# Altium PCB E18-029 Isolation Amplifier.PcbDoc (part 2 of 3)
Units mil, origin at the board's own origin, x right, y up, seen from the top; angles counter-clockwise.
Board outline 5740 x 5970 mil, 4 copper layers (Component Side, V+, V-, Ground), stack 33.234 mil thick; 359 components, 170 nets, 952 pads, 232 vias.
Unrouted connection lines stored in the file: 60.
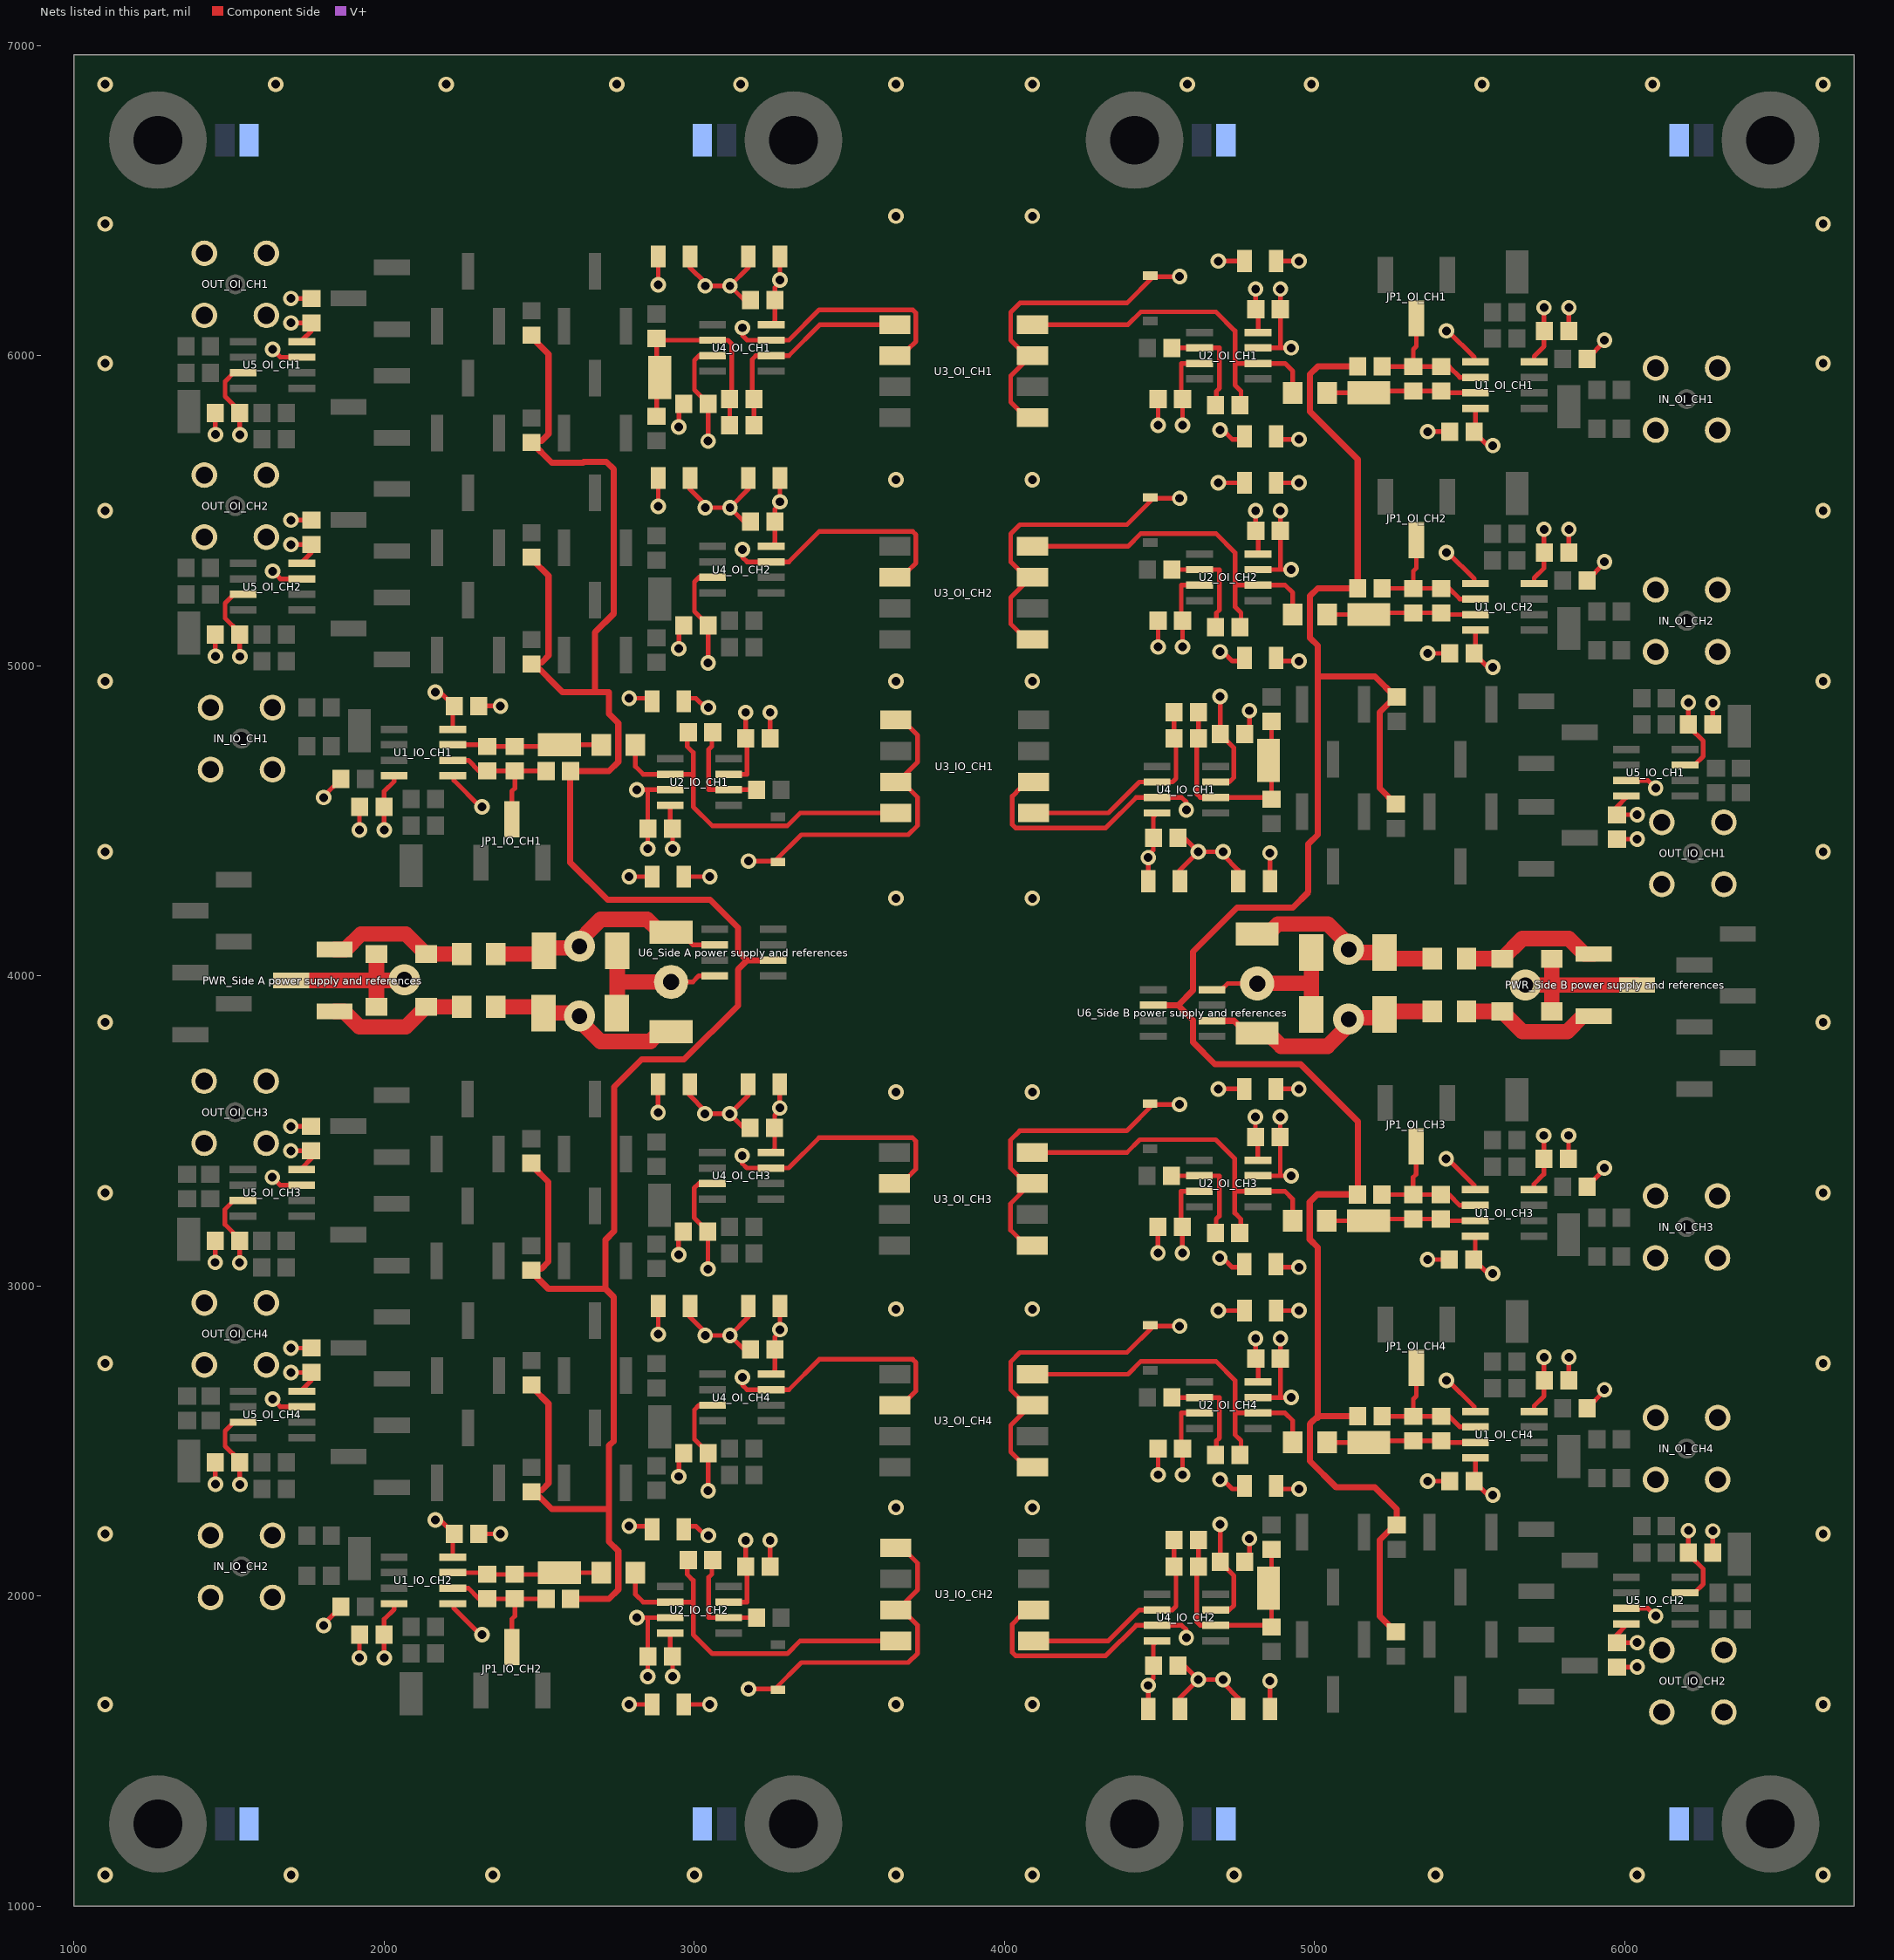
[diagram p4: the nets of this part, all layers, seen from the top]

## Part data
C1_IO_CH1 C1_IO_CH2 C1_OI_CH1 C1_OI_CH2 C1_OI_CH3 C1_OI_CH4 C2_IO_CH1 C2_IO_CH2 C2_OI_CH1 C2_OI_CH2 C2_OI_CH3 C2_OI_CH4 C3_IO_CH1 C3_IO_CH2 C3_OI_CH1 C3_OI_CH2 C3_OI_CH3 C3_OI_CH4 C4_IO_CH1 C4_IO_CH2 C4_OI_CH1 C4_OI_CH2 C4_OI_CH3 C4_OI_CH4 C6_IO_CH1 C6_IO_CH2 C6_OI_CH1 C6_OI_CH2 C6_OI_CH3 C6_OI_CH4 C7_IO_CH1 C7_IO_CH2 C7_OI_CH1 C7_OI_CH2 C7_OI_CH3 C7_OI_CH4 C8_IO_CH1 C8_IO_CH2 C8_OI_CH1 C8_OI_CH2 C8_OI_CH3 C8_OI_CH4 C9_IO_CH1 C9_IO_CH2 C9_OI_CH1 C9_OI_CH2 C9_OI_CH3 C9_OI_CH4 C14_IO_CH1 C14_IO_CH2 C14_OI_CH1 C14_OI_CH2 C14_OI_CH3 C14_OI_CH4 C15_IO_CH1 C15_IO_CH2 C15_OI_CH1 C15_OI_CH2 C15_OI_CH3 C15_OI_CH4 C16_IO_CH1 C16_IO_CH2 C16_OI_CH1 C16_OI_CH2 C16_OI_CH3 C16_OI_CH4 C17_IO_CH1 C17_IO_CH2 C17_OI_CH1 C17_OI_CH2 C17_OI_CH3 C17_OI_CH4: library part Cap, "Capacitor"
C10_IO_CH1 C10_IO_CH2 C10_OI_CH1 C10_OI_CH2 C10_OI_CH3 C10_OI_CH4 C11_IO_CH1 C11_IO_CH2 C11_OI_CH1 C11_OI_CH2 C11_OI_CH3 C11_OI_CH4 C12_IO_CH1 C12_IO_CH2 C12_OI_CH1 C12_OI_CH2 C12_OI_CH3 C12_OI_CH4 C13_IO_CH1 C13_IO_CH2 C13_OI_CH1 C13_OI_CH2 C13_OI_CH3 C13_OI_CH4: library part "Cap Pol3", "CAP TANT POLY 10UF 25V 1206"
"C18_Side A power supply and references" "C18_Side B power supply and references" "C19_Side A power supply and references" "C19_Side B power supply and references": library part "Cap Tant 100uF 10V", Manufacturer=AVX, Part Number=TCJE107M025R0080, Voltage=25V
D1_IO_CH1 D1_IO_CH2 D1_OI_CH1 D1_OI_CH2 D1_OI_CH3 D1_OI_CH4: "High Conductance Fast Diode", Manufacturer="Fairchild Semiconductor"
"D2_Side A power supply and references" "D2_Side B power supply and references" "D3_Side A power supply and references" "D3_Side B power supply and references": "Zener, 18V 1W SMAJ", Manufacturer=MCC, Part Number=SMAZ15-13-F
IN_IO_CH1 IN_IO_CH2 IN_OI_CH1 IN_OI_CH2 IN_OI_CH3 IN_OI_CH4 OUT_IO_CH1 OUT_IO_CH2 OUT_OI_CH1 OUT_OI_CH2 OUT_OI_CH3 OUT_OI_CH4: library part SMB_Male_Vertical, "SMA Male Vertical Mount", Manufacturer=Amphenol
JP1_IO_CH1 JP1_IO_CH2 JP1_OI_CH1 JP1_OI_CH2 JP1_OI_CH3 JP1_OI_CH4 JP2_IO_CH1 JP2_IO_CH2 JP2_OI_CH1 JP2_OI_CH2 JP2_OI_CH3 JP2_OI_CH4 JP3_IO_CH1 JP3_IO_CH2 JP3_OI_CH1 JP3_OI_CH2 JP3_OI_CH3 JP3_OI_CH4 "PWR_Side A power supply and references" "PWR_Side B power supply and references": library part Jumper3p, "3 Pin Jumper Header", Manufacturer="Generic Components"
JPA1 JPA2 JPA3 JPA4 JPB1 JPB2 JPB3 JPB4: library part Jumper2P_SMD, "2 Pin Jumper Solder Pads", Manufacturer="Generic Components"
Logo?: library part "Directive: Add UBC Logo to PCB", "UBC Logo"
MA1 MA2 MA3 MA4 MB1 MB2 MB3 MB4: library part "Mounting Pad", Manufacturer=AMP, Part No.=PAD_HV
PA PB: "0.1\" Spacing 1x6 Header", Manufacturer=AMP
R1_IO_CH1 R1_IO_CH2 R1_OI_CH1 R1_OI_CH2 R1_OI_CH3 R1_OI_CH4 R2_IO_CH1 R2_IO_CH2 R2_OI_CH1 R2_OI_CH2 R2_OI_CH3 R2_OI_CH4 R3_IO_CH1 R3_IO_CH2 R3_OI_CH1 R3_OI_CH2 R3_OI_CH3 R3_OI_CH4 R4_IO_CH1 R4_IO_CH2 R4_OI_CH1 R4_OI_CH2 R4_OI_CH3 R4_OI_CH4 R5_IO_CH1 R5_IO_CH2 R5_OI_CH1 R5_OI_CH2 R5_OI_CH3 R5_OI_CH4 R6_IO_CH1 R6_IO_CH2 R6_OI_CH1 R6_OI_CH2 R6_OI_CH3 R6_OI_CH4 R7_IO_CH1 R7_IO_CH2 R7_OI_CH1 R7_OI_CH2 R7_OI_CH3 R7_OI_CH4 R8_IO_CH1 R8_IO_CH2 R8_OI_CH1 R8_OI_CH2 R8_OI_CH3 R8_OI_CH4 R10_IO_CH1 R10_IO_CH2 R10_OI_CH1 R10_OI_CH2 R10_OI_CH3 R10_OI_CH4 R11_IO_CH1 R11_IO_CH2 R11_OI_CH1 R11_OI_CH2 R11_OI_CH3 R11_OI_CH4 R12_IO_CH1 R12_IO_CH2 R12_OI_CH1 R12_OI_CH2 R12_OI_CH3 R12_OI_CH4 R14_IO_CH1 R14_IO_CH2 R14_OI_CH1 R14_OI_CH2 R14_OI_CH3 R14_OI_CH4 R15_IO_CH1 R15_IO_CH2 R15_OI_CH1 R15_OI_CH2 R15_OI_CH3 R15_OI_CH4 R17_IO_CH1 R17_IO_CH2 R17_OI_CH1 R17_OI_CH2 R17_OI_CH3 R17_OI_CH4 R19_IO_CH1 R19_IO_CH2 R19_OI_CH1 R19_OI_CH2 R19_OI_CH3 R19_OI_CH4 R20_IO_CH1 R20_IO_CH2 R20_OI_CH1 R20_OI_CH2 R20_OI_CH3 R20_OI_CH4 R21_IO_CH1 R21_IO_CH2 R21_OI_CH1 R21_OI_CH2 R21_OI_CH3 R21_OI_CH4 "R27_Side A power supply and references" "R27_Side B power supply and references" "R28_Side A power supply and references" "R28_Side B power supply and references": library part Res1, "Resistor"
R9_IO_CH1 R9_IO_CH2 R9_OI_CH1 R9_OI_CH2 R9_OI_CH3 R9_OI_CH4 R13_IO_CH1 R13_IO_CH2 R13_OI_CH1 R13_OI_CH2 R13_OI_CH3 R13_OI_CH4 R16_IO_CH1 R16_IO_CH2 R16_OI_CH1 R16_OI_CH2 R16_OI_CH3 R16_OI_CH4 R18_IO_CH1 R18_IO_CH2 R18_OI_CH1 R18_OI_CH2 R18_OI_CH3 R18_OI_CH4: "SMD POT", Manufacturer=Vishay, Part Number=TS63Y
TP1_IO_CH1 TP1_IO_CH2 TP1_OI_CH1 TP1_OI_CH2 TP1_OI_CH3 TP1_OI_CH4 TP2_IO_CH1 TP2_IO_CH2 TP2_OI_CH1 TP2_OI_CH2 TP2_OI_CH3 TP2_OI_CH4 TP3_IO_CH1 TP3_IO_CH2 TP3_OI_CH1 TP3_OI_CH2 TP3_OI_CH3 TP3_OI_CH4 TP4_IO_CH1 TP4_IO_CH2 TP4_OI_CH1 TP4_OI_CH2 TP4_OI_CH3 TP4_OI_CH4 TP5_IO_CH1 TP5_IO_CH2 TP5_OI_CH1 TP5_OI_CH2 TP5_OI_CH3 TP5_OI_CH4 "TP+_Side A power supply and references" "TP+_Side B power supply and references" "TP-_Side A power supply and references" "TP-_Side B power supply and references" "TPCOM_Side A power supply and references" "TPCOM_Side B power supply and references": library part "TP- Eyelet Terminal", "Eyelet Test Point (white)", Manufacturer=Vero, Part Number=20-313143A
U1_IO_CH1 U1_IO_CH2 U1_OI_CH1 U1_OI_CH2 U1_OI_CH3 U1_OI_CH4 U5_IO_CH1 U5_IO_CH2 U5_OI_CH1 U5_OI_CH2 U5_OI_CH3 U5_OI_CH4: "OVP and EMI Protected, Precision, / Low Noise and Bias Current Dual Op Amp", Manufacturer="Analog Devices"
U2_IO_CH1 U2_IO_CH2 U2_OI_CH1 U2_OI_CH2 U2_OI_CH3 U2_OI_CH4: "36V, 18MHz, Low Noise, JFET Op Amp", Manufacturer="Analog Devices"
U3_IO_CH1 U3_IO_CH2 U3_OI_CH1 U3_OI_CH2 U3_OI_CH3 U3_OI_CH4: "Analog Optocoupler", Manufacturer=Agilent
U4_IO_CH1 U4_IO_CH2 U4_OI_CH1 U4_OI_CH2 U4_OI_CH3 U4_OI_CH4: "36V, 18MHz, Low Noise, JFET Op Amp", Manufacturer="Analog Devices", Part Number=AD548KR
"U6_Side A power supply and references" "U6_Side B power supply and references": "2ppm/°C, Low-Noise, +10V Voltage Reference", Manufacturer=Maxim, Part Number=MAX6325CSA

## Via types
v1: diameter 50, hole 28, Component Side to Ground, tented both sides, 226 vias
v2: diameter 100, hole 50, Component Side to Ground, tented both sides, 6 vias

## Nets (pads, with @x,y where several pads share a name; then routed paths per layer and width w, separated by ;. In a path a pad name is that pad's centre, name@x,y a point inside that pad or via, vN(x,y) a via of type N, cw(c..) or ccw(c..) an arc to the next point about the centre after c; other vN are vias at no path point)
+10REFA: "U6_Side A power supply and references.6" R1_IO_CH1.2 R1_IO_CH2.2 R8_OI_CH1.2 R8_OI_CH2.2 R8_OI_CH3.2 R8_OI_CH4.2 R11_OI_CH1.2 R11_OI_CH2.2 R11_OI_CH3.2 R11_OI_CH4.2 | length 7465.8
  Component Side w20: R11_OI_CH1.2@2475,5720 2540,5655 2641.11,5655 2643.33,5657.22 2716.67,5657.22 2740.69,5633.2 2740.69,5168.65 2680,5107.97 2680,4915.63 ; R11_OI_CH3.2@2477.83,3055.63 2507.17,3055.63 2529.37,3077.83 2529.37,3335 R8_OI_CH3.2@2479.37,3385 ; R11_OI_CH4.2@2478.46,2340.63 2507.8,2340.63 2530,2362.83 2530,2620 R8_OI_CH4.2@2480,2670 ; R11_OI_CH2.2@2478.46,5010.63 2507.8,5010.63 2530,5032.83 2530,5290 R8_OI_CH2.2@2480,5340 ; R11_OI_CH1.2@2478.46,5725.63 2507.8,5725.63 2530,5747.83 2530,6005 R8_OI_CH1.2@2480,6055 ; R11_OI_CH3.2@2479.37,3055 2479.37,3040.63 2530,2990 2713.89,2990 ; R11_OI_CH4.2@2480,2335 2480,2340 2540,2280 2725,2280 ; R11_OI_CH2.2@2480,5005 2480,5010 2574.37,4915.63 ; R11_OI_CH1.2@2480,5720 R11_OI_CH1.2@2480,5725 ; 2575,4915 2725,4915 2725,4845 2755,4815 2755,4690 2725,4660 R1_IO_CH1.2@2600.91,4660 2600,4660 2600,4365 2720,4245 3051.09,4245 3140.9,4155.18 3140.9,4079.1 3170,4050 ; R1_IO_CH2.2@2600,1990 R1_IO_CH2.2@2600.91,1990 2725,1990 2755,2020 2755,2145 2725,2175 2725,2280 ; 2740,2500 2725,2485 2725,2280 ; 2740.69,2498.65 2740.69,2963.2 2713.89,2990 ; 3254.49,4050 3170,4050 ; 2713.89,2990 2713.89,3148.89 2741.68,3176.68 2741.68,3641.68 2830,3730 2966.95,3730 3140.67,3903.72 3140.67,4020.67 3170,4050
+10REFB: "U6_Side B power supply and references.6" R1_OI_CH1.2 R1_OI_CH2.2 R1_OI_CH3.2 R1_OI_CH4.2 R8_IO_CH1.2 R8_IO_CH2.2 R11_IO_CH1.2 R11_IO_CH2.2 | length 6388
  Component Side w20: 4480.51,3905 4560,3905 ; 5010,2575 5010,2580 ; R1_OI_CH3.2@5134.37,3295 5009.37,3295 4984.37,3270 4984.37,3150 5010,3124.37 5010,2580 ; R1_OI_CH4.2@5135,2580 5010,2580 ; R1_OI_CH2.2@5135,5250 5010,5250 4985,5225 4985,5090 5010,5065 5010,4965 ; R1_OI_CH1.2@5135,5965 5010,5965 4985,5940 4985,5820 5139.09,5665.91 R1_OI_CH2.2@5139.09,5250 ; R1_OI_CH3.2@5140,3295 5140,3530 4955,3715 4678.91,3715 4608.18,3785.73 4608.18,3856.82 4560,3905 ; R8_IO_CH2.2@5260,1885 5210,1935 5210,2180 5259.37,2229.37 R11_IO_CH2.2@5265,2229.37 ; R8_IO_CH1.2@5260,4555 5210,4605 5210,4850 5259.37,4899.37 R11_IO_CH1.2@5265,4899.37 ; R11_IO_CH1.2@5260,4900 5195,4965 5010,4965 ; R11_IO_CH2.2@5265,2230 5265,2280 5195,2350 5070,2350 4985,2435 4985,2555 5010,2580 ; 4560,3905 4608.18,3953.18 4608.18,4078.18 4750,4220 4930,4220 4980,4270 4980,4425 5010,4455 5010,4965
+15A: "C18_Side A power supply and references.1" "R27_Side A power supply and references.1" "TP+_Side A power supply and references.1" "U6_Side A power supply and references.2" C6_IO_CH1.2 C6_IO_CH2.2 C7_IO_CH1.2 C7_IO_CH2.2 C8_OI_CH1.2 C8_OI_CH2.2 C8_OI_CH3.2 C8_OI_CH4.2 C9_OI_CH1.2 C9_OI_CH2.2 C9_OI_CH3.2 C9_OI_CH4.2 C10_IO_CH1.1 C10_IO_CH2.1 C11_OI_CH1.1 C11_OI_CH2.1 C11_OI_CH3.1 C11_OI_CH4.1 U1_IO_CH1.8 U1_IO_CH2.8 U2_IO_CH1.7 U2_IO_CH2.7 U4_OI_CH1.7 U4_OI_CH2.7 U4_OI_CH3.7 U4_OI_CH4.7 U5_OI_CH1.7 U5_OI_CH2.7 U5_OI_CH3.7 U5_OI_CH4.7 | length 4671.8
  Component Side w15: C9_OI_CH3.2@1516.07,3160.76 1518.61,3160.76 C9_OI_CH3.2@1534.37,3145 ; C9_OI_CH4.2@1516.7,2445.76 1519.24,2445.76 C9_OI_CH4.2@1535,2430 ; C9_OI_CH2.2@1516.7,5115.76 1519.24,5115.76 C9_OI_CH2.2@1535,5100 ; C9_OI_CH1.2@1516.7,5830.76 1519.24,5830.76 C9_OI_CH1.2@1535,5815 ; C9_OI_CH3.2@1529.37,3155 1486.07,3198.3 1486.07,3246.7 U5_OI_CH3.7@1514.37,3275 ; C9_OI_CH4.2@1530,2440 1486.7,2483.3 1486.7,2531.7 U5_OI_CH4.7@1515,2560 ; C9_OI_CH2.2@1530,5110 1486.7,5153.3 1486.7,5201.7 U5_OI_CH2.7@1515,5230 ; C9_OI_CH1.2@1530,5825 1486.7,5868.3 1486.7,5916.7 U5_OI_CH1.7@1515,5945 ; v1(1533.74,3074.37) C9_OI_CH3.2@1533.74,3145 ; v1(1534.37,2359.37) C9_OI_CH4.2@1534.37,2430 ; v1(1534.37,5029.37) C9_OI_CH2.2@1534.37,5100 ; v1(1534.37,5744.37) C9_OI_CH1.2@1534.37,5815 ; v1(2165,2245) 2180.63,2245 C6_IO_CH2.2@2225.63,2200 ; v1(2165,4915) 2180.63,4915 C6_IO_CH1.2@2225.63,4870 ; U1_IO_CH2.8@2221.02,2125 2221.02,2196.02 C6_IO_CH2.2@2225,2200 ; U1_IO_CH1.8@2221.02,4795 2221.02,4866.02 C6_IO_CH1.2@2225,4870 ; v1(2883.19,3558.82) C11_OI_CH3.1@2883.19,3650 ; v1(2883.82,2843.82) C11_OI_CH4.1@2883.82,2935 ; v1(2883.82,5513.82) C11_OI_CH2.1@2883.82,5605 ; v1(2883.82,6228.82) C11_OI_CH1.1@2883.82,6320 ; C10_IO_CH2.1@2966.18,2225 3005,2225 3035,2195 v1(3045,2195) ; C10_IO_CH1.1@2966.18,4895 3005,4895 3035,4865 v1(3045,4865) ; 2985,4110 2995,4100 3065.51,4100 ; v1(3043.74,3054.37) C8_OI_CH3.2@3043.74,3175 ; v1(3044.37,2339.37) C8_OI_CH4.2@3044.37,2460 ; C8_OI_CH3.2@3044.37,3175 2999.54,3219.83 2999.54,3315.17 3014.37,3330 U4_OI_CH3.7@3058.35,3330 ; v1(3044.37,5009.37) C8_OI_CH2.2@3044.37,5130 ; v1(3044.37,5724.37) C8_OI_CH1.2@3044.37,5845 ; C8_OI_CH4.2@3045,2460 3000.17,2504.83 3000.17,2600.17 3015,2615 U4_OI_CH4.7@3058.98,2615 ; C8_OI_CH2.2@3045,5130 3000.17,5174.83 3000.17,5270.17 3015,5285 U4_OI_CH2.7@3058.98,5285 ; C8_OI_CH1.2@3045,5845 3000.17,5889.83 3000.17,5985.17 3015,6000 U4_OI_CH1.7@3058.98,6000 ; U2_IO_CH2.7@3111.02,1980 3170,1980 C7_IO_CH2.2@3170,2095 ; U2_IO_CH1.7@3111.02,4650 3170,4650 C7_IO_CH1.2@3170,4765 ; C7_IO_CH2.2@3165.63,2095 v1(3165.63,2179.37) ; C7_IO_CH1.2@3165.63,4765 v1(3165.63,4849.37) ; U5_OI_CH3.7@1514.37,3275 U5_OI_CH3.7@1544.88,3275 U5_OI_CH3.7@1514.37,3275 ; U5_OI_CH4.7@1515,2560 U5_OI_CH4.7@1545.51,2560 U5_OI_CH4.7@1515,2560 ; U5_OI_CH2.7@1515,5230 U5_OI_CH2.7@1545.51,5230 U5_OI_CH2.7@1515,5230 ; U5_OI_CH1.7@1515,5945 U5_OI_CH1.7@1545.51,5945 U5_OI_CH1.7@1515,5945
  Component Side w20: 2925,4140 2955,4140
  Component Side w50: 2360.12,4070 2495,4070 2515,4090 2606.13,4090 2698.18,4182.06 2847.94,4182.06 2880,4150
  other v2: 2630,4095
+15B: "C18_Side B power supply and references.1" "R27_Side B power supply and references.1" "TP+_Side B power supply and references.1" "U6_Side B power supply and references.2" C6_OI_CH1.2 C6_OI_CH2.2 C6_OI_CH3.2 C6_OI_CH4.2 C7_OI_CH1.2 C7_OI_CH2.2 C7_OI_CH3.2 C7_OI_CH4.2 C8_IO_CH1.2 C8_IO_CH2.2 C9_IO_CH1.2 C9_IO_CH2.2 C10_OI_CH1.1 C10_OI_CH2.1 C10_OI_CH3.1 C10_OI_CH4.1 C11_IO_CH1.1 C11_IO_CH2.1 U1_OI_CH1.8 U1_OI_CH2.8 U1_OI_CH3.8 U1_OI_CH4.8 U2_OI_CH1.7 U2_OI_CH2.7 U2_OI_CH3.7 U2_OI_CH4.7 U4_IO_CH1.7 U4_IO_CH2.7 U5_IO_CH1.7 U5_IO_CH2.7 | length 4251.4
  Component Side w15: C7_OI_CH3.2@4569.37,3190 4569.37,3305 U2_OI_CH3.7@4628.35,3305 ; C7_OI_CH4.2@4570,2475 4570,2590 U2_OI_CH4.7@4628.98,2590 ; C7_OI_CH2.2@4570,5145 4570,5260 U2_OI_CH2.7@4628.98,5260 ; C7_OI_CH1.2@4570,5860 4570,5975 U2_OI_CH1.7@4628.98,5975 ; v1(4573.74,3105.63) C7_OI_CH3.2@4573.74,3190 ; v1(4574.37,2390.63) C7_OI_CH4.2@4574.37,2475 ; v1(4574.37,5060.63) C7_OI_CH2.2@4574.37,5145 ; v1(4574.37,5775.63) C7_OI_CH1.2@4574.37,5860 ; U4_IO_CH2.7@4681.02,1955 4725,1955 4739.83,1969.83 4739.83,2065.17 C8_IO_CH2.2@4695,2110 ; U4_IO_CH1.7@4681.02,4625 4725,4625 4739.83,4639.83 4739.83,4735.17 C8_IO_CH1.2@4695,4780 ; v1(4694.37,3090) 4704.37,3090 4734.37,3060 C10_OI_CH3.1@4773.19,3060 ; v1(4695,2375) 4705,2375 4735,2345 C10_OI_CH4.1@4773.82,2345 ; v1(4695,5045) 4705,5045 4735,5015 C10_OI_CH2.1@4773.82,5015 ; v1(4695,5760) 4705,5760 4735,5730 C10_OI_CH1.1@4773.82,5730 ; C8_IO_CH2.2@4695.63,2110 v1(4695.63,2230.63) ; C8_IO_CH1.2@4695.63,4780 v1(4695.63,4900.63) ; C11_IO_CH2.1@4856.18,1635 v1(4856.18,1726.18) ; C11_IO_CH1.1@4856.18,4305 v1(4856.18,4396.18) ; C6_OI_CH3.2@5513.74,3085 5558.74,3040 v1(5574.37,3040) ; C6_OI_CH4.2@5514.37,2370 5559.37,2325 v1(5575,2325) ; C6_OI_CH3.2@5514.37,3085 5518.35,3088.98 U1_OI_CH3.8@5518.35,3160 ; C6_OI_CH2.2@5514.37,5040 5559.37,4995 v1(5575,4995) ; C6_OI_CH1.2@5514.37,5755 5559.37,5710 v1(5575,5710) ; C6_OI_CH4.2@5515,2370 5518.98,2373.98 U1_OI_CH4.8@5518.98,2445 ; C6_OI_CH2.2@5515,5040 5518.98,5043.98 U1_OI_CH2.8@5518.98,5115 ; C6_OI_CH1.2@5515,5755 5518.98,5758.98 U1_OI_CH1.8@5518.98,5830 ; C9_IO_CH2.2@6205,2140 6220.76,2124.24 C9_IO_CH2.2@6223.3,2124.24 ; C9_IO_CH1.2@6205,4810 6220.76,4794.24 C9_IO_CH1.2@6223.3,4794.24 ; C9_IO_CH2.2@6205.63,2140 v1(6205.63,2210.63) ; C9_IO_CH1.2@6205.63,4810 v1(6205.63,4880.63) ; C9_IO_CH2.2@6210,2130 6253.3,2086.7 6253.3,2038.3 U5_IO_CH2.7@6225,2010 ; C9_IO_CH1.2@6210,4800 6253.3,4756.7 6253.3,4708.3 U5_IO_CH1.7@6225,4680 ; U5_IO_CH2.7@6225,2010 U5_IO_CH2.7@6194.49,2010 U5_IO_CH2.7@6225,2010 ; U5_IO_CH1.7@6225,4680 U5_IO_CH1.7@6194.49,4680 U5_IO_CH1.7@6225,4680
  Component Side w20: 4665,3855 4669.49,3855 4740,3855 4780,3815 4815,3815
  Component Side w50: 4860,3805 4892.06,3772.94 5041.82,3772.94 5133.87,3865 5225,3865 5245,3885 5379.88,3885
  other v2: 5110,3860
"+Vin_Side A power supply and references": "D2_Side A power supply and references.2" "PWR_Side A power supply and references.1" "R27_Side A power supply and references.2" | length 457.6
  Component Side w50: 1840,4085 1875,4085 1925,4135 2070,4135 2135,4070 2249.88,4070 2250,4070
"+Vin_Side B power supply and references": "D2_Side B power supply and references.2" "PWR_Side B power supply and references.1" "R27_Side B power supply and references.2" | length 457.6
  Component Side w50: 5490,3885 5490.12,3885 5605,3885 5670,3820 5815,3820 5865,3870 5900,3870
-15A: "C19_Side A power supply and references.2" "R28_Side A power supply and references.1" "TP-_Side A power supply and references.1" C12_IO_CH1.2 C12_IO_CH2.2 C13_OI_CH1.2 C13_OI_CH2.2 C13_OI_CH3.2 C13_OI_CH4.2 C14_IO_CH1.2 C14_IO_CH2.2 C15_IO_CH1.2 C15_IO_CH2.2 C16_OI_CH1.2 C16_OI_CH2.2 C16_OI_CH3.2 C16_OI_CH4.2 C17_OI_CH1.2 C17_OI_CH2.2 C17_OI_CH3.2 C17_OI_CH4.2 U1_IO_CH1.4 U1_IO_CH2.4 U2_IO_CH1.4 U2_IO_CH2.4 U4_OI_CH1.4 U4_OI_CH2.4 U4_OI_CH3.4 U4_OI_CH4.4 U5_OI_CH1.4 U5_OI_CH2.4 U5_OI_CH3.4 U5_OI_CH4.4 | length 2904.5
  Component Side w15: v1(1698.74,3435.63) C17_OI_CH3.2@1764.37,3435.63 ; v1(1699.37,2720.63) C17_OI_CH4.2@1765,2720.63 ; v1(1699.37,5390.63) C17_OI_CH2.2@1765,5390.63 ; v1(1699.37,6105.63) C17_OI_CH1.2@1765,6105.63 ; U5_OI_CH3.4@1733.86,3375 1733.86,3379.49 1764.37,3410 C17_OI_CH3.2@1764.37,3435 ; U5_OI_CH4.4@1734.49,2660 1734.49,2664.49 1765,2695 C17_OI_CH4.2@1765,2720 ; U5_OI_CH2.4@1734.49,5330 1734.49,5334.49 1765,5365 C17_OI_CH2.2@1765,5390 ; U5_OI_CH1.4@1734.49,6045 1734.49,6049.49 1765,6080 C17_OI_CH1.2@1765,6105 ; C14_IO_CH2.2@1999.37,1875 2000,1874.37 v1(2000,1800) ; C14_IO_CH1.2@1999.37,4545 2000,4544.37 v1(2000,4470) ; C14_IO_CH2.2@2000,1875 2000,1925 2032.05,1957.05 U1_IO_CH2.4@2032.05,1975 ; C14_IO_CH1.2@2000,4545 2000,4595 2032.05,4627.05 U1_IO_CH1.4@2032.05,4645 ; U2_IO_CH2.4@2922.05,1880 2922.05,1812.95 C15_IO_CH2.2@2930,1805 ; U2_IO_CH1.4@2922.05,4550 2922.05,4482.95 C15_IO_CH1.2@2930,4475 ; C15_IO_CH2.2@2929.37,1805 2930,1804.37 v1(2930,1740) ; C15_IO_CH1.2@2929.37,4475 2930,4474.37 v1(2930,4410) ; C12_IO_CH2.2@2966.18,1650 v1(3050,1650) ; C12_IO_CH1.2@2966.18,4320 v1(3050,4320) ; U4_OI_CH3.4@3247.32,3430 3259.37,3442.05 3259.37,3550 3275.55,3566.18 v1(3275.55,3573.82) C13_OI_CH3.2@3275.55,3650 ; U4_OI_CH4.4@3247.95,2715 3260,2727.05 3260,2835 3276.18,2851.18 v1(3276.18,2858.82) C13_OI_CH4.2@3276.18,2935 ; U4_OI_CH2.4@3247.95,5385 3260,5397.05 3260,5505 3276.18,5521.18 v1(3276.18,5528.82) C13_OI_CH2.2@3276.18,5605 ; U4_OI_CH1.4@3247.95,6100 3260,6112.05 3260,6220 3276.18,6236.18 v1(3276.18,6243.82) C13_OI_CH1.2@3276.18,6320
  Component Side w50: 2360.12,3900 2490,3900 2515,3875 ; 2513.78,3880 2604.91,3880 2696.96,3787.94 2857.94,3787.94 2890,3820
  other v2: 2630,3870
-15B: "C19_Side B power supply and references.2" "R28_Side B power supply and references.1" "TP-_Side B power supply and references.1" C12_OI_CH1.2 C12_OI_CH2.2 C12_OI_CH3.2 C12_OI_CH4.2 C13_IO_CH1.2 C13_IO_CH2.2 C14_OI_CH1.2 C14_OI_CH2.2 C14_OI_CH3.2 C14_OI_CH4.2 C15_OI_CH1.2 C15_OI_CH2.2 C15_OI_CH3.2 C15_OI_CH4.2 C16_IO_CH1.2 C16_IO_CH2.2 C17_IO_CH1.2 C17_IO_CH2.2 U1_OI_CH1.4 U1_OI_CH2.4 U1_OI_CH3.4 U1_OI_CH4.4 U2_OI_CH1.4 U2_OI_CH2.4 U2_OI_CH3.4 U2_OI_CH4.4 U4_IO_CH1.4 U4_IO_CH2.4 U5_IO_CH1.4 U5_IO_CH2.4 | length 2996.4
  Component Side w15: C13_IO_CH2.2@4463.82,1635 v1(4463.82,1711.18) 4463.82,1718.82 4480,1735 4480,1842.95 U4_IO_CH2.4@4492.05,1855 ; C13_IO_CH1.2@4463.82,4305 v1(4463.82,4381.18) 4463.82,4388.82 4480,4405 4480,4512.95 U4_IO_CH1.4@4492.05,4525 ; v1(4689.37,3635) C12_OI_CH3.2@4773.19,3635 ; v1(4690,2920) C12_OI_CH4.2@4773.82,2920 ; v1(4690,5590) C12_OI_CH2.2@4773.82,5590 ; v1(4690,6305) C12_OI_CH1.2@4773.82,6305 ; C15_OI_CH3.2@4809.37,3480 4817.32,3472.05 U2_OI_CH3.4@4817.32,3405 ; v1(4809.37,3545) 4809.37,3480.63 C15_OI_CH3.2@4810,3480 ; C15_OI_CH4.2@4810,2765 4817.95,2757.05 U2_OI_CH4.4@4817.95,2690 ; v1(4810,2830) 4810,2765.63 C15_OI_CH4.2@4810.63,2765 ; C15_OI_CH2.2@4810,5435 4817.95,5427.05 U2_OI_CH2.4@4817.95,5360 ; v1(4810,5500) 4810,5435.63 C15_OI_CH2.2@4810.63,5435 ; C15_OI_CH1.2@4810,6150 4817.95,6142.05 U2_OI_CH1.4@4817.95,6075 ; v1(4810,6215) 4810,6150.63 C15_OI_CH1.2@4810.63,6150 ; U1_OI_CH3.4@5707.32,3310 5707.32,3327.95 5739.37,3360 C14_OI_CH3.2@5739.37,3410 ; U1_OI_CH4.4@5707.95,2595 5707.95,2612.95 5740,2645 C14_OI_CH4.2@5740,2695 ; U1_OI_CH2.4@5707.95,5265 5707.95,5282.95 5740,5315 C14_OI_CH2.2@5740,5365 ; U1_OI_CH1.4@5707.95,5980 5707.95,5997.95 5740,6030 C14_OI_CH1.2@5740,6080 ; v1(5739.37,3485) 5739.37,3410.63 C14_OI_CH3.2@5740,3410 ; v1(5740,2770) 5740,2695.63 C14_OI_CH4.2@5740.63,2695 ; v1(5740,5440) 5740,5365.63 C14_OI_CH2.2@5740.63,5365 ; v1(5740,6155) 5740,6080.63 C14_OI_CH1.2@5740.63,6080 ; C17_IO_CH2.2@5975,1849.37 v1(6040.63,1849.37) ; C17_IO_CH2.2@5975,1850 5975,1875 6005.51,1905.51 U5_IO_CH2.4@6005.51,1910 ; C17_IO_CH1.2@5975,4519.37 v1(6040.63,4519.37) ; C17_IO_CH1.2@5975,4520 5975,4545 6005.51,4575.51 U5_IO_CH1.4@6005.51,4580
  Component Side w50: 4850,4135 4882.06,4167.06 5043.04,4167.06 5135.09,4075 5226.22,4075 ; 5225,4080 5250,4055 5379.88,4055
  other v2: 5110,4085
"-Vin_Side A power supply and references": "D3_Side A power supply and references.1" "PWR_Side A power supply and references.3" "R28_Side A power supply and references.2" | length 457.6
  Component Side w50: 1840,3885 1870,3885 1920,3835 2070,3835 2135,3900 2249.88,3900 2250,3900
"-Vin_Side B power supply and references": "D3_Side B power supply and references.1" "PWR_Side B power supply and references.3" "R28_Side B power supply and references.2" | length 457.6
  Component Side w50: 5490,4055 5490.12,4055 5605,4055 5670,4120 5820,4120 5870,4070 5900,4070
COMA: "C18_Side A power supply and references.2" "C19_Side A power supply and references.1" "D2_Side A power supply and references.1" "D3_Side A power supply and references.2" "PWR_Side A power supply and references.2" "TPCOM_Side A power supply and references.1" "U6_Side A power supply and references.4" C6_IO_CH1.1 C6_IO_CH2.1 C7_IO_CH1.1 C7_IO_CH2.1 C8_OI_CH1.1 C8_OI_CH2.1 C8_OI_CH3.1 C8_OI_CH4.1 C9_OI_CH1.1 C9_OI_CH2.1 C9_OI_CH3.1 C9_OI_CH4.1 C10_IO_CH1.2 C10_IO_CH2.2 C11_OI_CH1.2 C11_OI_CH2.2 C11_OI_CH3.2 C11_OI_CH4.2 C12_IO_CH1.1 C12_IO_CH2.1 C13_OI_CH1.1 C13_OI_CH2.1 C13_OI_CH3.1 C13_OI_CH4.1 C14_IO_CH1.1 C14_IO_CH2.1 C15_IO_CH1.1 C15_IO_CH2.1 C16_OI_CH1.1 C16_OI_CH2.1 C16_OI_CH3.1 C16_OI_CH4.1 C17_OI_CH1.1 C17_OI_CH2.1 C17_OI_CH3.1 C17_OI_CH4.1 D1_IO_CH1.1 D1_IO_CH2.1 IN_IO_CH1.2 IN_IO_CH2.2 JPA1.2 JPA2.2 JPA3.2 JPA4.2 OUT_OI_CH1.2 OUT_OI_CH2.2 OUT_OI_CH3.2 OUT_OI_CH4.2 R7_IO_CH1.1 R7_IO_CH2.1 U1_IO_CH1.5 U1_IO_CH2.5 U2_IO_CH1.3 U2_IO_CH2.3 U3_IO_CH1.1 U3_IO_CH1.3 U3_IO_CH2.1 U3_IO_CH2.3 U3_OI_CH1.6 U3_OI_CH2.6 U3_OI_CH3.6 U3_OI_CH4.6 U4_OI_CH1.3 U4_OI_CH2.3 U4_OI_CH3.3 U4_OI_CH4.3 U5_OI_CH1.3 U5_OI_CH2.3 U5_OI_CH3.3 U5_OI_CH4.3 | length 10932.8
  Component Side w15: v1(1455,3075.63) C9_OI_CH3.1@1455,3145 ; v1(1455.63,2360.63) C9_OI_CH4.1@1455.63,2430 ; v1(1455.63,5030.63) C9_OI_CH2.1@1455.63,5100 ; v1(1455.63,5745.63) C9_OI_CH1.1@1455.63,5815 ; v1(1639.37,3350) 1664.37,3325 U5_OI_CH3.3@1733.86,3325 ; v1(1640,2635) 1665,2610 U5_OI_CH4.3@1734.49,2610 ; v1(1640,5305) 1665,5280 U5_OI_CH2.3@1734.49,5280 ; v1(1640,6020) 1665,5995 U5_OI_CH1.3@1734.49,5995 ; v1(1698.74,3514.37) C17_OI_CH3.1@1764.37,3514.37 ; v1(1699.37,2799.37) C17_OI_CH4.1@1765,2799.37 ; v1(1699.37,5469.37) C17_OI_CH2.1@1765,5469.37 ; v1(1699.37,6184.37) C17_OI_CH1.1@1765,6184.37 ; v1(1805,1905) 1805,1909.37 R7_IO_CH2.1@1860.63,1965 ; v1(1805,4575) 1805,4579.37 R7_IO_CH1.1@1860.63,4635 ; v1(1920,1800) 1920,1874.37 C14_IO_CH2.1@1920.63,1875 ; v1(1920,4470) 1920,4544.37 C14_IO_CH1.1@1920.63,4545 ; U1_IO_CH2.5@2221.02,1975 2225,1971.02 2225,1960 2310,1875 v1(2315,1875) ; U1_IO_CH1.5@2221.02,4645 2225,4641.02 2225,4630 2310,4545 v1(2315,4545) ; C6_IO_CH2.1@2304.37,2200 v1(2375,2200) ; C6_IO_CH1.1@2304.37,4870 v1(2375,4870) ; v1(2790,1650) C12_IO_CH2.1@2863.82,1650 ; v1(2790,2225) C10_IO_CH2.2@2858.82,2225 ; v1(2790,4320) C12_IO_CH1.1@2863.82,4320 ; v1(2790,4895) C10_IO_CH1.2@2858.82,4895 ; v1(2815,1930) 2850,1930 ; v1(2815,4600) 2850,4600 ; v1(2850,1740) 2850,1930 ; v1(2850,4410) 2850,4600 ; U2_IO_CH2.3@2922.05,1930 2850,1930 ; U2_IO_CH1.3@2922.05,4600 2850,4600 ; 2925,3980 2995,3980 3015,4000 3065.51,4000 ; v1(2949.37,3100) 2949.37,3159.37 C8_OI_CH3.1@2965,3175 ; v1(2950,2385) 2950,2444.37 C8_OI_CH4.1@2965.63,2460 ; v1(2950,5055) 2950,5114.37 C8_OI_CH2.1@2965.63,5130 ; v1(2950,5770) 2950,5829.37 C8_OI_CH1.1@2965.63,5845 ; C11_OI_CH3.2@2984.37,3615 3034.37,3565 v1(3034.37,3555) v1(3114.37,3555) ; C11_OI_CH4.2@2985,2900 3035,2850 v1(3035,2840) v1(3115,2840) ; C11_OI_CH2.2@2985,5570 3035,5520 v1(3035,5510) v1(3115,5510) ; C11_OI_CH1.2@2985,6285 3035,6235 v1(3035,6225) v1(3115,6225) ; v1(3154.37,3420) 3154.37,3395 3169.37,3380 U4_OI_CH3.3@3247.32,3380 3304.37,3380 3402.37,3478 3703.29,3478 3713.83,3467.46 3713.83,3376 3687.83,3350 3665.83,3350 U3_OI_CH3.6@3645.83,3330 U3_OI_CH3.6@3624.37,3330 ; v1(3155,2705) 3155,2680 3170,2665 U4_OI_CH4.3@3247.95,2665 3305,2665 3403,2763 3703.92,2763 3714.46,2752.46 3714.46,2661 3688.46,2635 3666.46,2635 U3_OI_CH4.6@3646.46,2615 U3_OI_CH4.6@3625,2615 ; v1(3155,5375) 3155,5350 3170,5335 U4_OI_CH2.3@3247.95,5335 3305,5335 3403,5433 3703.92,5433 3714.46,5422.46 3714.46,5331 3688.46,5305 3666.46,5305 U3_OI_CH2.6@3646.46,5285 U3_OI_CH2.6@3625,5285 ; v1(3155,6090) 3155,6065 3170,6050 U4_OI_CH1.3@3247.95,6050 3305,6050 3403,6148 3703.92,6148 3714.46,6137.46 3714.46,6046 3688.46,6020 3666.46,6020 U3_OI_CH1.6@3646.46,6000 U3_OI_CH1.6@3625,6000 ; C13_OI_CH3.1@3174.37,3620 3174.37,3615 v1(3114.37,3555) ; v1(3175,1700) 3260,1700 3345,1785 3690,1785 3720,1815 3720,1905 U3_IO_CH2.3@3662.5,1962.5 ; C13_OI_CH4.1@3175,2905 3175,2900 v1(3115,2840) ; v1(3175,4370) 3260,4370 3345,4455 3690,4455 3720,4485 3720,4575 U3_IO_CH1.3@3662.5,4632.5 ; C13_OI_CH2.1@3175,5575 3175,5570 v1(3115,5510) ; C13_OI_CH1.1@3175,6290 3175,6285 v1(3115,6225) ; C16_OI_CH3.1@3180,3510 3159.37,3510 v1(3114.37,3555) ; C16_OI_CH4.1@3180.63,2795 3160,2795 v1(3115,2840) ; C16_OI_CH2.1@3180.63,5465 3160,5465 v1(3115,5510) ; C16_OI_CH1.1@3180.63,6180 3160,6180 v1(3115,6225) ; C7_IO_CH2.1@3244.37,2095 v1(3244.37,2179.37) ; C7_IO_CH1.1@3244.37,4765 v1(3244.37,4849.37) ; U3_IO_CH2.3@3649.54,1955 U3_IO_CH2.3@3651.46,1955 ; U3_IO_CH1.3@3649.54,4625 U3_IO_CH1.3@3651.46,4625 ; U3_IO_CH2.1@3651.54,2155 3670,2155 3720,2105 3720,2020.01 U3_IO_CH2.3@3662.5,1962.5 ; U3_IO_CH1.1@3651.54,4825 3670,4825 3720,4775 3720,4690.01 U3_IO_CH1.3@3662.5,4632.5 ; U3_IO_CH2.3@3662.5,1962.5 3659.77,1965.23 3654.99,1970.01 3654.99,1955 U3_IO_CH2.3@3662.5,1962.5 ; U3_IO_CH1.3@3662.5,4632.5 3659.77,4635.23 3654.99,4640.01 3654.99,4625 U3_IO_CH1.3@3662.5,4632.5
  Component Side w50: 1700,3985 1975,3985 ; 1975,3900 1975,3985 ; 1975,4070 1975,3985 ; v2(2065,3987.5) 2062.5,3985 1975,3985 ; 2750,3880 2751.22,3881.22 2751.22,3980 ; 2751.22,4080 2751.22,3980 ; 2925,3980 2751.22,3980
  V+ w15: v1(3244.37,2179.37) v1@3245,2180 ; v1(3244.37,4849.37) v1@3245,4850
  other v1: 1100,1100 1700,1100 2350,1100 3000,1100 3650,1100 1100,1650 3650,1650 1100,2200 3650,2285 1100,2750 3650,2925 1100,3300 3650,3625 1100,3850 3650,4250 1100,4400 1100,4950 3650,4950 1100,5500 3650,5600 1100,5975 1100,6425 3650,6450 1100,6875 1650,6875 2200,6875 2750,6875 3150,6875 3650,6875
COMB: "C18_Side B power supply and references.2" "C19_Side B power supply and references.1" "D2_Side B power supply and references.1" "D3_Side B power supply and references.2" "PWR_Side B power supply and references.2" "TPCOM_Side B power supply and references.1" "U6_Side B power supply and references.4" C6_OI_CH1.1 C6_OI_CH2.1 C6_OI_CH3.1 C6_OI_CH4.1 C7_OI_CH1.1 C7_OI_CH2.1 C7_OI_CH3.1 C7_OI_CH4.1 C8_IO_CH1.1 C8_IO_CH2.1 C9_IO_CH1.1 C9_IO_CH2.1 C10_OI_CH1.2 C10_OI_CH2.2 C10_OI_CH3.2 C10_OI_CH4.2 C11_IO_CH1.2 C11_IO_CH2.2 C12_OI_CH1.1 C12_OI_CH2.1 C12_OI_CH3.1 C12_OI_CH4.1 C13_IO_CH1.1 C13_IO_CH2.1 C14_OI_CH1.1 C14_OI_CH2.1 C14_OI_CH3.1 C14_OI_CH4.1 C15_OI_CH1.1 C15_OI_CH2.1 C15_OI_CH3.1 C15_OI_CH4.1 C16_IO_CH1.1 C16_IO_CH2.1 C17_IO_CH1.1 C17_IO_CH2.1 D1_OI_CH1.1 D1_OI_CH2.1 D1_OI_CH3.1 D1_OI_CH4.1 IN_OI_CH1.2 IN_OI_CH2.2 IN_OI_CH3.2 IN_OI_CH4.2 JPB1.2 JPB2.2 JPB3.2 JPB4.2 OUT_IO_CH1.2 OUT_IO_CH2.2 R7_OI_CH1.1 R7_OI_CH2.1 R7_OI_CH3.1 R7_OI_CH4.1 U1_OI_CH1.5 U1_OI_CH2.5 U1_OI_CH3.5 U1_OI_CH4.5 U2_OI_CH1.3 U2_OI_CH2.3 U2_OI_CH3.3 U2_OI_CH4.3 U3_IO_CH1.6 U3_IO_CH2.6 U3_OI_CH1.1 U3_OI_CH1.3 U3_OI_CH2.1 U3_OI_CH2.3 U3_OI_CH3.1 U3_OI_CH3.3 U3_OI_CH4.1 U3_OI_CH4.3 U4_IO_CH1.3 U4_IO_CH2.3 U5_IO_CH1.3 U5_IO_CH2.3 | length 11852.3
  Component Side w15: U3_OI_CH3.1@4087.83,3130 4069.37,3130 4019.37,3180 4019.37,3264.99 U3_OI_CH3.3@4076.87,3322.5 ; U3_OI_CH3.3@4087.91,3330 U3_OI_CH3.3@4089.83,3330 ; U3_OI_CH4.1@4088.46,2415 4070,2415 4020,2465 4020,2549.99 U3_OI_CH4.3@4077.5,2607.5 ; U3_OI_CH2.1@4088.46,5085 4070,5085 4020,5135 4020,5219.99 U3_OI_CH2.3@4077.5,5277.5 ; U3_OI_CH1.1@4088.46,5800 4070,5800 4020,5850 4020,5934.99 U3_OI_CH1.3@4077.5,5992.5 ; U3_OI_CH4.3@4088.54,2615 U3_OI_CH4.3@4090.46,2615 ; U3_OI_CH2.3@4088.54,5285 U3_OI_CH2.3@4090.46,5285 ; U3_OI_CH1.3@4088.54,6000 U3_OI_CH1.3@4090.46,6000 ; U3_IO_CH2.6@4115,1955 U3_IO_CH2.6@4093.54,1955 4073.54,1935 4051.54,1935 4025.54,1909 4025.54,1817.54 4036.08,1807 4327,1807 4425,1905 U4_IO_CH2.3@4490,1905 ; U3_IO_CH1.6@4115,4625 U3_IO_CH1.6@4093.54,4625 4073.54,4605 4051.54,4605 4025.54,4579 4025.54,4487.54 4036.08,4477 4327,4477 4425,4575 U4_IO_CH1.3@4490,4575 ; U4_IO_CH2.3@4493.58,1905 4571.54,1905 4586.54,1890 v1(4586.54,1865) ; U4_IO_CH1.3@4493.58,4575 4571.54,4575 4586.54,4560 v1(4586.54,4535) ; v1(4495,3105.63) C7_OI_CH3.1@4495,3190 ; v1(4495.63,2390.63) C7_OI_CH4.1@4495.63,2475 ; v1(4495.63,5060.63) C7_OI_CH2.1@4495.63,5145 ; v1(4495.63,5775.63) C7_OI_CH1.1@4495.63,5860 ; C16_IO_CH2.1@4559.37,1775 4580,1775 v1(4625,1730) ; C16_IO_CH1.1@4559.37,4445 4580,4445 v1(4625,4400) ; v1(4564.37,3585) 4479.37,3585 4394.37,3500 4049.37,3500 4019.37,3470 4019.37,3380 U3_OI_CH3.3@4076.87,3322.5 ; C13_IO_CH2.1@4565,1665 4565,1670 v1(4625,1730) ; v1(4565,2870) 4480,2870 4395,2785 4050,2785 4020,2755 4020,2665 U3_OI_CH4.3@4077.5,2607.5 ; C13_IO_CH1.1@4565,4335 4565,4340 v1(4625,4400) ; v1(4565,5540) 4480,5540 4395,5455 4050,5455 4020,5425 4020,5335 U3_OI_CH2.3@4077.5,5277.5 ; v1(4565,6255) 4480,6255 4395,6170 4050,6170 4020,6140 4020,6050 U3_OI_CH1.3@4077.5,5992.5 ; 4669.49,3955 4700,3955 4720,3975 4815,3975 ; C11_IO_CH2.2@4755,1670 4705,1720 v1(4705,1730) v1(4625,1730) ; C11_IO_CH1.2@4755,4340 4705,4390 v1(4705,4400) v1(4625,4400) ; C8_IO_CH2.1@4774.37,2110 4790,2125.63 v1(4790,2185) ; C8_IO_CH1.1@4774.37,4780 4790,4795.63 v1(4790,4855) ; U2_OI_CH3.3@4817.32,3355 4889.37,3355 ; U2_OI_CH4.3@4817.95,2640 4890,2640 ; U2_OI_CH2.3@4817.95,5310 4890,5310 ; U2_OI_CH1.3@4817.95,6025 4890,6025 ; C12_OI_CH3.1@4875.55,3635 v1(4949.37,3635) ; C12_OI_CH4.1@4876.18,2920 v1(4950,2920) ; C12_OI_CH2.1@4876.18,5590 v1(4950,5590) ; C12_OI_CH1.1@4876.18,6305 v1(4950,6305) ; C10_OI_CH3.2@4880.55,3060 v1(4949.37,3060) ; C10_OI_CH4.2@4881.18,2345 v1(4950,2345) ; C10_OI_CH2.2@4881.18,5015 v1(4950,5015) ; C10_OI_CH1.2@4881.18,5730 v1(4950,5730) ; v1(4889.37,3545) 4889.37,3355 ; v1(4890,2830) 4890,2640 ; v1(4890,5500) 4890,5310 ; v1(4890,6215) 4890,6025 ; v1(4924.37,3355) 4889.37,3355 ; v1(4925,2640) 4890,2640 ; v1(4925,5310) 4890,5310 ; v1(4925,6025) 4890,6025 ; v1(5364.37,3085) C6_OI_CH3.1@5435,3085 ; v1(5365,2370) C6_OI_CH4.1@5435.63,2370 ; v1(5365,5040) C6_OI_CH2.1@5435.63,5040 ; v1(5365,5755) C6_OI_CH1.1@5435.63,5755 ; v1(5424.37,3410) 5429.37,3410 5514.37,3325 5514.37,3313.98 U1_OI_CH3.5@5518.35,3310 ; v1(5425,2695) 5430,2695 5515,2610 5515,2598.98 U1_OI_CH4.5@5518.98,2595 ; v1(5425,5365) 5430,5365 5515,5280 5515,5268.98 U1_OI_CH2.5@5518.98,5265 ; v1(5425,6080) 5430,6080 5515,5995 5515,5983.98 U1_OI_CH1.5@5518.98,5980 ; C14_OI_CH3.1@5818.74,3410 5819.37,3410.63 v1(5819.37,3485) ; C14_OI_CH4.1@5819.37,2695 5820,2695.63 v1(5820,2770) ; C14_OI_CH2.1@5819.37,5365 5820,5365.63 v1(5820,5440) ; C14_OI_CH1.1@5819.37,6080 5820,6080.63 v1(5820,6155) ; R7_OI_CH3.1@5878.74,3320 5934.37,3375.63 v1(5934.37,3380) ; R7_OI_CH4.1@5879.37,2605 5935,2660.63 v1(5935,2665) ; R7_OI_CH2.1@5879.37,5275 5935,5330.63 v1(5935,5335) ; R7_OI_CH1.1@5879.37,5990 5935,6045.63 v1(5935,6050) ; C17_IO_CH2.1@5975,1770.63 v1(6040.63,1770.63) ; C17_IO_CH1.1@5975,4440.63 v1(6040.63,4440.63) ; U5_IO_CH2.3@6005.51,1960 6075,1960 v1(6100,1935) ; U5_IO_CH1.3@6005.51,4630 6075,4630 v1(6100,4605) ; C9_IO_CH2.1@6284.37,2140 v1(6284.37,2209.37) ; C9_IO_CH1.1@6284.37,4810 v1(6284.37,4879.37) ; U3_OI_CH3.3@4076.87,3322.5 4084.38,3330 4084.38,3314.99 4079.6,3319.77 U3_OI_CH3.3@4076.87,3322.5 ; U3_OI_CH4.3@4077.5,2607.5 4085.01,2615 4085.01,2599.99 4080.23,2604.77 U3_OI_CH4.3@4077.5,2607.5 ; U3_OI_CH2.3@4077.5,5277.5 4085.01,5285 4085.01,5269.99 4080.23,5274.77 U3_OI_CH2.3@4077.5,5277.5 ; U3_OI_CH1.3@4077.5,5992.5 4085.01,6000 4085.01,5984.99 4080.23,5989.77 U3_OI_CH1.3@4077.5,5992.5
  Component Side w50: 4815,3975 4815.61,3975.61 4990,3975.61 ; 4988.78,3875 4990,3876.22 4990,3975.61 ; 4990,4075 4990,3975.61 ; v2(5680,3970) 5765,3970 ; 5765,3885 5765,3970 ; 5765,4055 5765,3970 ; 6040,3970 5765,3970
  V+ w15: v1@4494.37,3105 v1(4495,3105.63) ; v1@4495,2390 v1(4495.63,2390.63) ; v1@4495,5060 v1(4495.63,5060.63) ; v1@4495,5775 v1(4495.63,5775.63)
  other v1: 4090,1100 4740,1100 5390,1100 6040,1100 6640,1100 4090,1650 6640,1650 6640,2200 4090,2285 6640,2750 4090,2925 6640,3300 4090,3625 6640,3850 4090,4250 6640,4400 4090,4950 6640,4950 6640,5500 4090,5600 6640,5975 6640,6425 4090,6450 4090,6875 4590,6875 4990,6875 5540,6875 6090,6875 6640,6875
NetC1_IO_CH1_1: C1_IO_CH1.1 R2_IO_CH1.1 R4_IO_CH1.1 TP3_IO_CH1.1 U1_IO_CH1.7 | length 493.6
  Component Side w15: U1_IO_CH1.7@2221.02,4745 2331.54,4745 R2_IO_CH1.1@2336.54,4740 ; R2_IO_CH1.1@2331.54,4740 R2_IO_CH1.1@2332.17,4739.37 C1_IO_CH1.1@2421.54,4739.37 2559.37,4739.37 TP3_IO_CH1.1@2565,4745 R4_IO_CH1.1@2699.88,4745 R4_IO_CH1.1@2705,4745
NetC1_IO_CH1_2: C1_IO_CH1.2 JP1_IO_CH1.2 R1_IO_CH1.1 R2_IO_CH1.2 U1_IO_CH1.6 | length 472.4
  Component Side w15: U1_IO_CH1.6@2226.54,4695 2271.54,4695 2305.91,4660.63 2420.91,4660.63 2421.54,4660 2421.54,4605 2411.54,4595 JP1_IO_CH1.2@2411.54,4505 ; C1_IO_CH1.2@2421.54,4660.63 2524.37,4660.63 R1_IO_CH1.1@2525,4660
NetC1_IO_CH2_1: C1_IO_CH2.1 R2_IO_CH2.1 R4_IO_CH2.1 TP3_IO_CH2.1 U1_IO_CH2.7 | length 493.6
  Component Side w15: U1_IO_CH2.7@2221.02,2075 2331.54,2075 R2_IO_CH2.1@2336.54,2070 ; R2_IO_CH2.1@2331.54,2070 R2_IO_CH2.1@2332.17,2069.37 C1_IO_CH2.1@2421.54,2069.37 2559.37,2069.37 TP3_IO_CH2.1@2565,2075 R4_IO_CH2.1@2699.88,2075 R4_IO_CH2.1@2705,2075
NetC1_IO_CH2_2: C1_IO_CH2.2 JP1_IO_CH2.2 R1_IO_CH2.1 R2_IO_CH2.2 U1_IO_CH2.6 | length 472.4
  Component Side w15: U1_IO_CH2.6@2226.54,2025 2271.54,2025 2305.91,1990.63 2420.91,1990.63 2421.54,1990 2421.54,1935 2411.54,1925 JP1_IO_CH2.2@2411.54,1835 ; C1_IO_CH2.2@2421.54,1990.63 2524.37,1990.63 R1_IO_CH2.1@2525,1990
NetC1_OI_CH1_1: C1_OI_CH1.1 R2_OI_CH1.1 R4_OI_CH1.1 TP3_OI_CH1.1 U1_OI_CH1.7 | length 493.6
  Component Side w15: R4_OI_CH1.1@5035,5880 R4_OI_CH1.1@5040.12,5880 TP3_OI_CH1.1@5175,5880 5180.63,5885.63 C1_OI_CH1.1@5318.46,5885.63 R2_OI_CH1.1@5407.83,5885.63 R2_OI_CH1.1@5408.46,5885 ; R2_OI_CH1.1@5403.46,5885 5408.46,5880 U1_OI_CH1.7@5518.98,5880
NetC1_OI_CH1_2: C1_OI_CH1.2 JP1_OI_CH1.2 R1_OI_CH1.1 R2_OI_CH1.2 U1_OI_CH1.6 | length 472.4
  Component Side w15: R1_OI_CH1.1@5215,5965 5215.63,5964.37 C1_OI_CH1.2@5318.46,5964.37 ; JP1_OI_CH1.2@5328.46,6120 5328.46,6030 5318.46,6020 5318.46,5965 5319.09,5964.37 5434.09,5964.37 5468.46,5930 U1_OI_CH1.6@5513.46,5930
NetC1_OI_CH2_1: C1_OI_CH2.1 R2_OI_CH2.1 R4_OI_CH2.1 TP3_OI_CH2.1 U1_OI_CH2.7 | length 493.6
  Component Side w15: R4_OI_CH2.1@5035,5165 R4_OI_CH2.1@5040.12,5165 TP3_OI_CH2.1@5175,5165 5180.63,5170.63 C1_OI_CH2.1@5318.46,5170.63 R2_OI_CH2.1@5407.83,5170.63 R2_OI_CH2.1@5408.46,5170 ; R2_OI_CH2.1@5403.46,5170 5408.46,5165 U1_OI_CH2.7@5518.98,5165
NetC1_OI_CH2_2: C1_OI_CH2.2 JP1_OI_CH2.2 R1_OI_CH2.1 R2_OI_CH2.2 U1_OI_CH2.6 | length 472.4
  Component Side w15: R1_OI_CH2.1@5215,5250 5215.63,5249.37 C1_OI_CH2.2@5318.46,5249.37 ; JP1_OI_CH2.2@5328.46,5405 5328.46,5315 5318.46,5305 5318.46,5250 5319.09,5249.37 5434.09,5249.37 5468.46,5215 U1_OI_CH2.6@5513.46,5215
NetC1_OI_CH3_1: C1_OI_CH3.1 R2_OI_CH3.1 R4_OI_CH3.1 TP3_OI_CH3.1 U1_OI_CH3.7 | length 493.6
  Component Side w15: R4_OI_CH3.1@5034.37,3210 R4_OI_CH3.1@5039.49,3210 TP3_OI_CH3.1@5174.37,3210 5180,3215.63 C1_OI_CH3.1@5317.83,3215.63 R2_OI_CH3.1@5407.2,3215.63 R2_OI_CH3.1@5407.83,3215 ; R2_OI_CH3.1@5402.83,3215 5407.83,3210 U1_OI_CH3.7@5518.35,3210
NetC1_OI_CH3_2: C1_OI_CH3.2 JP1_OI_CH3.2 R1_OI_CH3.1 R2_OI_CH3.2 U1_OI_CH3.6 | length 472.4
  Component Side w15: R1_OI_CH3.1@5214.37,3295 5215,3294.37 C1_OI_CH3.2@5317.83,3294.37 ; JP1_OI_CH3.2@5327.83,3450 5327.83,3360 5317.83,3350 5317.83,3295 5318.46,3294.37 5433.46,3294.37 5467.83,3260 U1_OI_CH3.6@5512.83,3260
NetC1_OI_CH4_1: C1_OI_CH4.1 R2_OI_CH4.1 R4_OI_CH4.1 TP3_OI_CH4.1 U1_OI_CH4.7 | length 493.6
  Component Side w15: R4_OI_CH4.1@5035,2495 R4_OI_CH4.1@5040.12,2495 TP3_OI_CH4.1@5175,2495 5180.63,2500.63 C1_OI_CH4.1@5318.46,2500.63 R2_OI_CH4.1@5407.83,2500.63 R2_OI_CH4.1@5408.46,2500 ; R2_OI_CH4.1@5403.46,2500 5408.46,2495 U1_OI_CH4.7@5518.98,2495
NetC1_OI_CH4_2: C1_OI_CH4.2 JP1_OI_CH4.2 R1_OI_CH4.1 R2_OI_CH4.2 U1_OI_CH4.6 | length 472.4
  Component Side w15: R1_OI_CH4.1@5215,2580 5215.63,2579.37 C1_OI_CH4.2@5318.46,2579.37 ; JP1_OI_CH4.2@5328.46,2735 5328.46,2645 5318.46,2635 5318.46,2580 5319.09,2579.37 5434.09,2579.37 5468.46,2545 U1_OI_CH4.6@5513.46,2545
NetC2_IO_CH1_1: C2_IO_CH1.1 R5_IO_CH1.1 U2_IO_CH1.6 | length 342.6
  Component Side w15: C2_IO_CH1.1@3056.54,4780 3056.54,4740 3046.54,4730 3046.54,4600 U2_IO_CH1.6@3111.02,4600 R5_IO_CH1.1@3200.63,4600 R5_IO_CH1.1@3205,4600
NetC2_IO_CH1_2: C2_IO_CH1.2 R4_IO_CH1.2 U2_IO_CH1.2 U3_IO_CH1.4 | length 1217.6
  Component Side w15: R4_IO_CH1.2@2810.12,4745 2810.12,4674.88 2835,4650 U2_IO_CH1.2@2922.05,4650 2996.54,4650 ; C2_IO_CH1.2@2977.17,4780 2977.17,4739.37 2996.54,4720 2996.54,4650 ; U3_IO_CH1.4@3649.54,4525 U3_IO_CH1.4@3655,4525 ; U3_IO_CH1.4@3650,4510 3635,4525 3341.49,4525 3300.04,4483.55 3057.98,4483.55 2996.54,4545 2996.54,4650
NetC2_IO_CH2_1: C2_IO_CH2.1 R5_IO_CH2.1 U2_IO_CH2.6 | length 342.6
  Component Side w15: C2_IO_CH2.1@3056.54,2110 3056.54,2070 3046.54,2060 3046.54,1930 U2_IO_CH2.6@3111.02,1930 R5_IO_CH2.1@3200.63,1930 R5_IO_CH2.1@3205,1930
NetC2_IO_CH2_2: C2_IO_CH2.2 R4_IO_CH2.2 U2_IO_CH2.2 U3_IO_CH2.4 | length 1217.6
  Component Side w15: R4_IO_CH2.2@2810.12,2075 2810.12,2004.88 2835,1980 U2_IO_CH2.2@2922.05,1980 2996.54,1980 ; C2_IO_CH2.2@2977.17,2110 2977.17,2069.37 2996.54,2050 2996.54,1980 ; U3_IO_CH2.4@3649.54,1855 U3_IO_CH2.4@3655,1855 ; U3_IO_CH2.4@3650,1840 3635,1855 3341.49,1855 3300.04,1813.55 3057.98,1813.55 2996.54,1875 2996.54,1980
NetC2_OI_CH1_1: C2_OI_CH1.1 R5_OI_CH1.1 U2_OI_CH1.6 | length 342.6
  Component Side w15: R5_OI_CH1.1@4535,6025 R5_OI_CH1.1@4539.37,6025 U2_OI_CH1.6@4628.98,6025 4693.46,6025 4693.46,5895 4683.46,5885 C2_OI_CH1.1@4683.46,5845
NetC2_OI_CH1_2: C2_OI_CH1.2 R4_OI_CH1.2 U2_OI_CH1.2 U3_OI_CH1.4 | length 1217.6
  Component Side w15: U3_OI_CH1.4@4085,6100 U3_OI_CH1.4@4090.46,6100 ; U3_OI_CH1.4@4090,6115 4105,6100 4398.51,6100 4439.96,6141.45 4682.02,6141.45 4743.46,6080 4743.46,5975 ; C2_OI_CH1.2@4762.83,5845 4762.83,5885.63 4743.46,5905 4743.46,5975 ; R4_OI_CH1.2@4929.88,5880 4929.88,5950.12 4905,5975 U2_OI_CH1.2@4817.95,5975 4743.46,5975
NetC2_OI_CH2_1: C2_OI_CH2.1 R5_OI_CH2.1 U2_OI_CH2.6 | length 342.6
  Component Side w15: R5_OI_CH2.1@4535,5310 R5_OI_CH2.1@4539.37,5310 U2_OI_CH2.6@4628.98,5310 4693.46,5310 4693.46,5180 4683.46,5170 C2_OI_CH2.1@4683.46,5130
NetC2_OI_CH2_2: C2_OI_CH2.2 R4_OI_CH2.2 U2_OI_CH2.2 U3_OI_CH2.4 | length 1217.6
  Component Side w15: U3_OI_CH2.4@4085,5385 U3_OI_CH2.4@4090.46,5385 ; U3_OI_CH2.4@4090,5400 4105,5385 4398.51,5385 4439.96,5426.45 4682.02,5426.45 4743.46,5365 4743.46,5260 ; C2_OI_CH2.2@4762.83,5130 4762.83,5170.63 4743.46,5190 4743.46,5260 ; R4_OI_CH2.2@4929.88,5165 4929.88,5235.12 4905,5260 U2_OI_CH2.2@4817.95,5260 4743.46,5260
NetC2_OI_CH3_1: C2_OI_CH3.1 R5_OI_CH3.1 U2_OI_CH3.6 | length 342.6
  Component Side w15: R5_OI_CH3.1@4534.37,3355 R5_OI_CH3.1@4538.74,3355 U2_OI_CH3.6@4628.35,3355 4692.83,3355 4692.83,3225 4682.83,3215 C2_OI_CH3.1@4682.83,3175
NetC2_OI_CH3_2: C2_OI_CH3.2 R4_OI_CH3.2 U2_OI_CH3.2 U3_OI_CH3.4 | length 1217.6
  Component Side w15: U3_OI_CH3.4@4084.37,3430 U3_OI_CH3.4@4089.83,3430 ; U3_OI_CH3.4@4089.37,3445 4104.37,3430 4395,3430 4436.45,3471.45 4681.39,3471.45 4742.83,3410 4742.83,3305 ; C2_OI_CH3.2@4762.2,3175 4762.2,3215.63 4742.83,3235 4742.83,3305 ; R4_OI_CH3.2@4929.25,3210 4929.25,3280.12 4904.37,3305 U2_OI_CH3.2@4817.32,3305 4742.83,3305
NetC2_OI_CH4_1: C2_OI_CH4.1 R5_OI_CH4.1 U2_OI_CH4.6 | length 342.6
  Component Side w15: R5_OI_CH4.1@4535,2640 R5_OI_CH4.1@4539.37,2640 U2_OI_CH4.6@4628.98,2640 4693.46,2640 4693.46,2510 4683.46,2500 C2_OI_CH4.1@4683.46,2460
NetC2_OI_CH4_2: C2_OI_CH4.2 R4_OI_CH4.2 U2_OI_CH4.2 U3_OI_CH4.4 | length 1217.6
  Component Side w15: U3_OI_CH4.4@4085,2715 U3_OI_CH4.4@4090.46,2715 ; U3_OI_CH4.4@4090,2730 4105,2715 4398.51,2715 4439.96,2756.45 4682.02,2756.45 4743.46,2695 4743.46,2590 ; C2_OI_CH4.2@4762.83,2460 4762.83,2500.63 4743.46,2520 4743.46,2590 ; R4_OI_CH4.2@4929.88,2495 4929.88,2565.12 4905,2590 U2_OI_CH4.2@4817.95,2590 4743.46,2590
NetC3_IO_CH1_1: C3_IO_CH1.1 R10_IO_CH1.2 R14_IO_CH1.2 R17_IO_CH1.2 TP4_IO_CH1.1 U4_IO_CH1.6 | length 819.3
  Component Side w15: R10_IO_CH1.2@4625.91,4765 4619.72,4758.81 4619.72,4586.82 4631.54,4575 U4_IO_CH1.6@4681.02,4575 ; C3_IO_CH1.1@4625.91,4850 4625.91,4765.63 R10_IO_CH1.2@4626.54,4765 ; 4636.02,4575 4856.54,4575 R14_IO_CH1.2@4861.54,4570 ; R14_IO_CH1.2@4861.54,4569.37 4861.54,4685 TP4_IO_CH1.1@4851.54,4695 4861.54,4705 R17_IO_CH1.2@4861.54,4820.63
NetC3_IO_CH1_2: C3_IO_CH1.2 R10_IO_CH1.1 U3_IO_CH1.5 U4_IO_CH1.2 | length 724.1
  Component Side w15: U3_IO_CH1.5@4091.54,4525 U3_IO_CH1.5@4093.54,4525 4335,4525 4435,4625 U4_IO_CH1.2@4492.05,4625 4541.54,4625 4553.36,4636.82 4553.36,4758.81 R10_IO_CH1.1@4547.17,4765 ; R10_IO_CH1.1@4546.54,4765 4547.17,4765.63 C3_IO_CH1.2@4547.17,4850
NetC3_IO_CH2_1: C3_IO_CH2.1 R10_IO_CH2.2 R14_IO_CH2.2 R17_IO_CH2.2 TP4_IO_CH2.1 U4_IO_CH2.6 | length 819.3
  Component Side w15: R10_IO_CH2.2@4625.91,2095 4619.72,2088.81 4619.72,1916.82 4631.54,1905 U4_IO_CH2.6@4681.02,1905 ; C3_IO_CH2.1@4625.91,2180 4625.91,2095.63 R10_IO_CH2.2@4626.54,2095 ; 4636.02,1905 4856.54,1905 R14_IO_CH2.2@4861.54,1900 ; R14_IO_CH2.2@4861.54,1899.37 4861.54,2015 TP4_IO_CH2.1@4851.54,2025 4861.54,2035 R17_IO_CH2.2@4861.54,2150.63
NetC3_IO_CH2_2: C3_IO_CH2.2 R10_IO_CH2.1 U3_IO_CH2.5 U4_IO_CH2.2 | length 724.1
  Component Side w15: U3_IO_CH2.5@4091.54,1855 U3_IO_CH2.5@4093.54,1855 4335,1855 4435,1955 U4_IO_CH2.2@4492.05,1955 4541.54,1955 4553.36,1966.82 4553.36,2088.81 R10_IO_CH2.1@4547.17,2095 ; R10_IO_CH2.1@4546.54,2095 4547.17,2095.63 C3_IO_CH2.2@4547.17,2180
NetC3_OI_CH1_1: C3_OI_CH1.1 R10_OI_CH1.2 R14_OI_CH1.2 R17_OI_CH1.2 TP4_OI_CH1.1 U4_OI_CH1.6 | length 819.3
  Component Side w15: R17_OI_CH1.2@2878.46,5804.37 2878.46,5920 TP4_OI_CH1.1@2888.46,5930 2878.46,5940 R14_OI_CH1.2@2878.46,6055.63 ; R14_OI_CH1.2@2878.46,6055 2883.46,6050 3103.98,6050 ; U4_OI_CH1.6@3058.98,6050 3108.46,6050 3120.28,6038.18 3120.28,5866.19 R10_OI_CH1.2@3114.09,5860 ; R10_OI_CH1.2@3113.46,5860 3114.09,5859.37 C3_OI_CH1.1@3114.09,5775
NetC3_OI_CH1_2: C3_OI_CH1.2 R10_OI_CH1.1 U3_OI_CH1.5 U4_OI_CH1.2 | length 724.1
  Component Side w15: C3_OI_CH1.2@3192.83,5775 3192.83,5859.37 R10_OI_CH1.1@3193.46,5860 ; R10_OI_CH1.1@3192.83,5860 3186.64,5866.19 3186.64,5988.18 3198.46,6000 U4_OI_CH1.2@3247.95,6000 3305,6000 3405,6100 U3_OI_CH1.5@3646.46,6100 U3_OI_CH1.5@3648.46,6100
